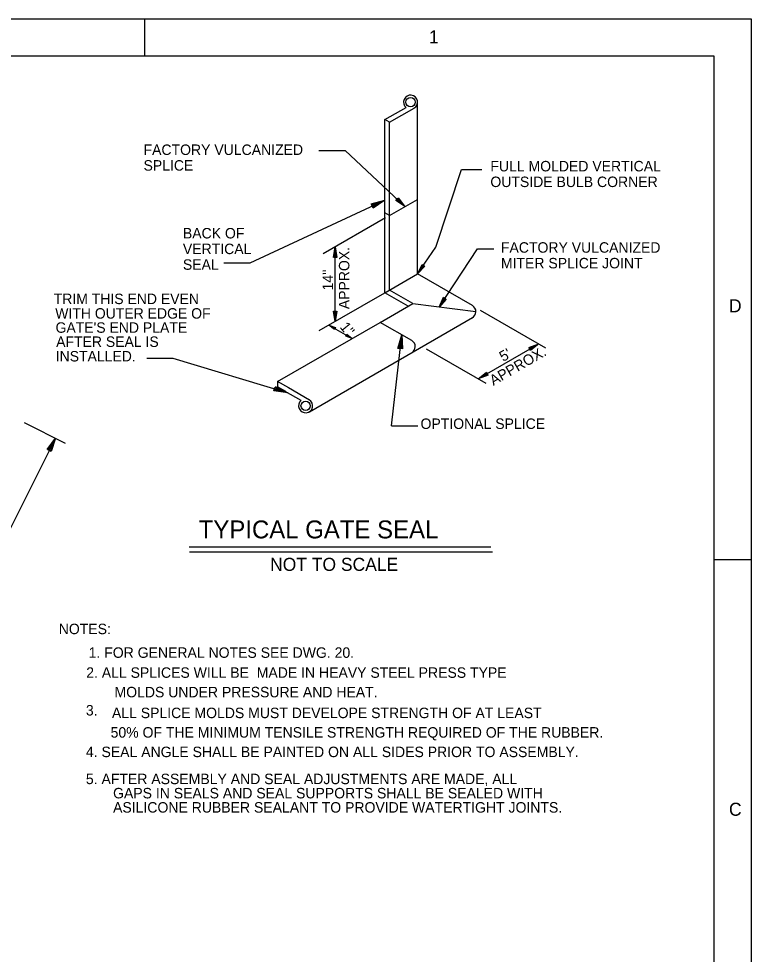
# Model space of a CAD drawing. Extents: x 0.1 to 13.5, y 0.1 to 9.5.
# Drawn here: x 10.186 to 13.458, y 5.277 to 9.458 of the extents above; entities that cross this region are included whole.
import ezdxf

# ---------------------------------------------------------------- set-up
doc = ezdxf.new("R2010")
doc.units = 0
for name, color, linetype in [('Level 1', 7, 'Continuous'), ('Level 2', 7, 'Continuous'), ('Level 25', 7, 'Continuous'), ('Level 3', 7, 'Continuous'), ('Level 50', 7, 'Continuous')]:
    doc.layers.add(name, color=color, linetype=linetype)

msp = doc.modelspace()

# ---------------------------------------------------------------- linework, layer by layer
at = {"layer": 'Level 1'}
for p, q in [((10.75, 9.2917), (10.75, 9.4583)), ((10.2103, 7.654), (10.3944, 7.562)), ((10.3502, 7.5841), (9.9309, 6.7456)), ((13.2917, 7.0417), (13.4583, 7.0417))]:
    msp.add_line(p, q, dxfattribs=at)
for points in [[(0.125, 9.4583), (13.4583, 9.4583), (13.4583, 0.125), (0.125, 0.125)], [(0.625, 9.2917), (13.2917, 9.2917), (13.2917, 0.2917), (0.625, 0.2917)]]:
    msp.add_lwpolyline(points, close=True, dxfattribs=at)
at = {"layer": 'Level 2'}
for p, q in [((11.9678, 8.3177), (11.9678, 9.0857)), ((11.822, 9.0075), (11.9163, 9.0619)), ((11.8428, 8.9955), (11.9524, 9.0587)), ((11.822, 8.2334), (11.822, 9.0075)), ((11.8428, 8.9955), (11.822, 9.0075)), ((11.8428, 8.2455), (11.8428, 8.9955)), ((11.8428, 8.5788), (11.9678, 8.6509)), ((11.8428, 8.5788), (11.822, 8.5908)), ((11.822, 8.2334), (11.9678, 8.3177)), ((12.2127, 8.1763), (11.9678, 8.3177)), ((11.947, 8.1854), (11.8428, 8.2455)), ((11.9262, 8.1733), (11.822, 8.2334)), ((11.8012, 8.1012), (11.947, 8.1854)), ((11.947, 8.1854), (12.2283, 8.1493)), ((11.4847, 7.7019), (12.2137, 8.1228)), ((11.3428, 7.8365), (11.8012, 8.1011)), ((11.9418, 8.0199), (11.8012, 8.1012)), ((11.3428, 7.8365), (11.3428, 7.8125)), ((11.3921, 7.8081), (11.3429, 7.8365)), ((11.3787, 7.7918), (11.3428, 7.8125)), ((11.4476, 7.752), (11.3769, 7.7929)), ((11.4853, 7.7543), (11.3913, 7.8086))]:
    msp.add_line(p, q, dxfattribs=at)
for centre in [(11.9366, 9.0857), (11.4679, 7.7283)]:
    msp.add_circle(centre, 0.0208, dxfattribs=at)
for centre, start, end in [((11.9366, 9.0857), 298.7423, 229.4899), ((12.197, 8.1493), 297.5644, 59.9802), ((11.9262, 7.9929), 297.5644, 59.9802), ((11.4679, 7.7283), 130.5179, 59.9802)]:
    msp.add_arc(centre, 0.0313, start, end, dxfattribs=at)
at = {"layer": 'Level 25'}
for p, q in [((11.2203, 8.3671), (11.822, 8.6476)), ((11.851, 7.6391), (11.8969, 8.0459)), ((10.8753, 7.9416), (11.3879, 7.7865))]:
    msp.add_line(p, q, dxfattribs=at)
at = {"layer": 'Level 3'}
for p, q in [((11.5265, 8.8689), (11.6445, 8.8689)), ((11.9095, 8.6199), (11.6445, 8.8689)), ((12.0499, 8.4374), (12.164, 8.7845)), ((12.164, 8.7845), (12.2548, 8.7845)), ((11.9001, 8.6288), (11.9001, 8.6288)), ((11.9095, 8.6199), (11.9095, 8.6199)), ((11.8245, 8.5682), (11.5469, 8.4079)), ((11.5997, 8.1051), (11.5997, 8.4384)), ((11.5997, 8.4384), (11.5997, 8.4384)), ((11.5997, 8.4254), (11.5997, 8.4254)), ((11.9678, 8.3177), (12.0499, 8.4374)), ((12.0639, 8.1699), (12.236, 8.4304)), ((12.236, 8.4304), (12.3081, 8.4304)), ((11.103, 8.3671), (11.2203, 8.3671)), ((11.9752, 8.3284), (11.9752, 8.3284)), ((11.9678, 8.3177), (11.9678, 8.3177)), ((11.529, 8.0643), (11.822, 8.2334)), ((12.0639, 8.1699), (12.0639, 8.1699)), ((12.071, 8.1808), (12.071, 8.1808)), ((12.2469, 8.1565), (12.5394, 7.9877)), ((11.5997, 8.1181), (11.5997, 8.1181)), ((11.5722, 8.0892), (11.6763, 8.0291)), ((11.5722, 8.0892), (11.5722, 8.0892)), ((11.5797, 8.0849), (11.5797, 8.0849)), ((11.5997, 8.1051), (11.5997, 8.1051)), ((11.6688, 8.0334), (11.6688, 8.0334)), ((11.6763, 8.0291), (11.6763, 8.0291)), ((12.2387, 7.8486), (12.5095, 8.0049)), ((12.4983, 7.9984), (12.4983, 7.9984)), ((12.5095, 8.0049), (12.5095, 8.0049)), ((12.0068, 7.9824), (12.2724, 7.8291)), ((10.758, 7.9416), (10.8753, 7.9416)), ((12.2387, 7.8486), (12.2387, 7.8486)), ((12.2499, 7.8551), (12.2499, 7.8551)), ((11.851, 7.6391), (11.9683, 7.6391)), ((10.9473, 7.0981), (12.2954, 7.0981)), ((10.9488, 7.0761), (12.3029, 7.0761))]:
    msp.add_line(p, q, dxfattribs=at)
for points in [[(11.8808, 8.6575), (11.9095, 8.6199), (11.8702, 8.6462), (11.8793, 8.6559), (11.9001, 8.6288), (11.8733, 8.6467), (11.8792, 8.6529), (11.891, 8.6373), (11.8765, 8.6471), (11.8789, 8.6497), (11.8815, 8.6462)], [(11.5919, 8.3917), (11.5997, 8.4384), (11.6074, 8.3917), (11.5942, 8.3917), (11.5997, 8.4254), (11.6049, 8.3937), (11.5964, 8.3937), (11.5997, 8.4129), (11.6024, 8.3957), (11.5989, 8.3957), (11.5997, 8.3999)], [(12.0007, 8.3518), (11.9678, 8.3177), (11.9879, 8.3606), (11.9988, 8.3531), (11.9752, 8.3284), (11.9888, 8.3575), (11.9958, 8.3527), (11.9823, 8.3387), (11.9898, 8.3545), (11.9926, 8.3525), (11.9896, 8.3494)], [(12.0961, 8.2047), (12.0639, 8.1699), (12.0832, 8.2132), (12.0943, 8.2059), (12.071, 8.1808), (12.0842, 8.2102), (12.0913, 8.2055), (12.0779, 8.1912), (12.0852, 8.2071), (12.0881, 8.2052), (12.0851, 8.2021)], [(11.6074, 8.1518), (11.5997, 8.1051), (11.5919, 8.1518), (11.6052, 8.1518), (11.5997, 8.1181), (11.5944, 8.1498), (11.6029, 8.1498), (11.5997, 8.1306), (11.5969, 8.1478), (11.6004, 8.1478), (11.5997, 8.1436)], [(11.5966, 8.0692), (11.5722, 8.0892), (11.6018, 8.0781), (11.5973, 8.0704), (11.5797, 8.0849), (11.5998, 8.0773), (11.5969, 8.0724), (11.5869, 8.0807), (11.5978, 8.0765), (11.5966, 8.0745), (11.5944, 8.0764)], [(11.6519, 8.0491), (11.6763, 8.0291), (11.6468, 8.0402), (11.6512, 8.0478), (11.6688, 8.0334), (11.6488, 8.0409), (11.6516, 8.0459), (11.6616, 8.0376), (11.6508, 8.0417), (11.6519, 8.0437), (11.6541, 8.0419)], [(12.4651, 7.9883), (12.5095, 8.0049), (12.4729, 7.9749), (12.4663, 7.9863), (12.4983, 7.9984), (12.4734, 7.978), (12.4691, 7.9854), (12.4874, 7.9922), (12.4738, 7.9812), (12.4721, 7.9842), (12.4762, 7.9857)], [(12.283, 7.8652), (12.2387, 7.8486), (12.2753, 7.8787), (12.2819, 7.8672), (12.2499, 7.8551), (12.2748, 7.8755), (12.279, 7.8681), (12.2608, 7.8613), (12.2743, 7.8723), (12.2761, 7.8693), (12.272, 7.8678)]]:
    msp.add_lwpolyline(points, dxfattribs=at)
at = {"layer": 'Level 50'}
for p, q in [((11.8063, 8.6403), (11.8063, 8.6403)), ((11.822, 8.6476), (11.822, 8.6476)), ((11.8949, 8.0287), (11.8949, 8.0287)), ((11.8969, 8.0459), (11.8969, 8.0459)), ((11.3714, 7.7915), (11.3714, 7.7915)), ((11.3879, 7.7865), (11.3879, 7.7865)), ((10.3424, 7.5686), (10.3424, 7.5686)), ((10.3502, 7.5841), (10.3502, 7.5841))]:
    msp.add_line(p, q, dxfattribs=at)
for points in [[(11.7611, 8.6307), (11.822, 8.6476), (11.7699, 8.6119), (11.7624, 8.6279), (11.8063, 8.6403), (11.7709, 8.6161), (11.7661, 8.6264), (11.7912, 8.6333), (11.7719, 8.6202), (11.7699, 8.6245), (11.7755, 8.6259)], [(11.8796, 7.9851), (11.8969, 8.0459), (11.9002, 7.9828), (11.8826, 7.9848), (11.8949, 8.0287), (11.8971, 7.9858), (11.8859, 7.9871), (11.8931, 8.0121), (11.8941, 7.9889), (11.8895, 7.9894), (11.8911, 7.9949)], [(11.3313, 7.8144), (11.3879, 7.7865), (11.3253, 7.7946), (11.3304, 7.8116), (11.3714, 7.7915), (11.3288, 7.7971), (11.3321, 7.8079), (11.3554, 7.7963), (11.3323, 7.7995), (11.3337, 7.8039), (11.3388, 7.8014)], [(10.3131, 7.5329), (10.3502, 7.5841), (10.3316, 7.5237), (10.3158, 7.5316), (10.3424, 7.5686), (10.3298, 7.5276), (10.3196, 7.5326), (10.335, 7.5537), (10.328, 7.5314), (10.3238, 7.5335), (10.3272, 7.5381)]]:
    msp.add_lwpolyline(points, dxfattribs=at)

# ---------------------------------------------------------------- texts
at = {"layer": 'Level 1'}
for s, height, p in [('1', 0.0584, (12.0186, 9.348)), ('TRIM THIS END EVEN', 0.046698, (10.3426, 8.183)), ('D', 0.0584, (13.3587, 8.1461)), ('WITH OUTER EDGE OF', 0.046698, (10.3495, 8.118)), ("GATE'S END PLATE", 0.046698, (10.351, 8.0548)), ('AFTER SEAL IS', 0.046698, (10.3536, 7.9916)), ('INSTALLED.', 0.0467, (10.3516, 7.9266)), ('NOT TO SCALE', 0.058333, (11.3091, 6.9907)), ('C', 0.0584, (13.3587, 5.8961))]:
    msp.add_text(s, height=height, dxfattribs=at).set_placement(p)
at = {"layer": 'Level 3'}
for s, height, p in [('FACTORY VULCANIZED', 0.046792, (10.7438, 8.8494)), ('SPLICE', 0.04679, (10.7438, 8.7794)), ('FULL MOLDED VERTICAL', 0.046792, (12.293, 8.776)), ('OUTSIDE BULB CORNER', 0.046792, (12.293, 8.706)), ('BACK OF', 0.04679, (10.9197, 8.4763)), ('VERTICAL', 0.04679, (10.9197, 8.4063)), ('FACTORY VULCANIZED', 0.046792, (12.3401, 8.4126)), ('SEAL', 0.04679, (10.9197, 8.3363)), ('MITER SPLICE JOINT', 0.046792, (12.3401, 8.3426)), ('OPTIONAL SPLICE', 0.046792, (11.981, 7.625)), ('TYPICAL GATE SEAL', 0.08, (10.9904, 7.1359)), ('NOTES:', 0.04679, (10.3652, 6.7079)), ('1. FOR GENERAL NOTES SEE DWG. 20.', 0.046792, (10.4987, 6.6021)), ('2. ALL SPLICES WILL BE  MADE IN HEAVY STEEL PRESS TYPE', 0.046792, (10.4878, 6.5128)), ('MOLDS UNDER PRESSURE AND HEAT.', 0.046792, (10.6142, 6.4256)), ('3.', 0.04679, (10.4865, 6.3443)), ('ALL SPLICE MOLDS MUST DEVELOPE STRENGTH OF AT LEAST', 0.046792, (10.6026, 6.3326)), ('50% OF THE MINIMUM TENSILE STRENGTH REQUIRED OF THE RUBBER.', 0.046792, (10.5968, 6.2455)), ('4. SEAL ANGLE SHALL BE PAINTED ON ALL SIDES PRIOR TO ASSEMBLY.', 0.046792, (10.4865, 6.1584)), ('5. AFTER ASSEMBLY AND SEAL ADJUSTMENTS ARE MADE, ALL', 0.046792, (10.4865, 6.0376)), ('GAPS IN SEALS AND SEAL SUPPORTS SHALL BE SEALED WITH', 0.046792, (10.6078, 5.974)), ('ASILICONE RUBBER SEALANT TO PROVIDE WATERTIGHT JOINTS.', 0.046792, (10.6078, 5.9104))]:
    msp.add_text(s, height=height, dxfattribs=at).set_placement(p)
for s, rotation, p in [('APPROX.', 90, (11.6633, 8.1602)), ("14''", 90, (11.5903, 8.2438)), ('1"', 309.0065, (11.6182, 8.0797)), ('APPROX.', 30.0015, (12.3064, 7.8173)), ("5'", 30.0015, (12.35, 7.9239))]:
    msp.add_text(s, height=0.04679, rotation=rotation, dxfattribs=at).set_placement(p)

doc.saveas('drawing.dxf')
